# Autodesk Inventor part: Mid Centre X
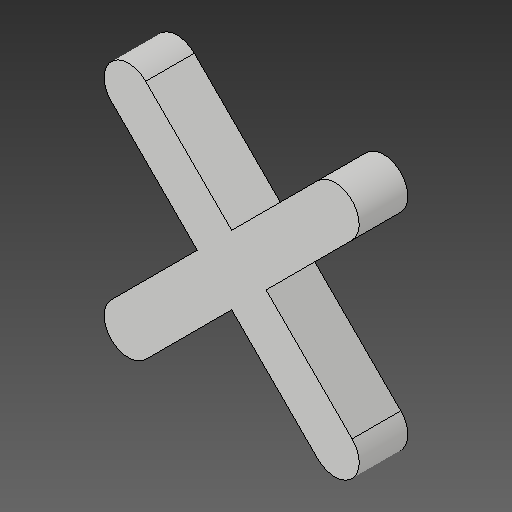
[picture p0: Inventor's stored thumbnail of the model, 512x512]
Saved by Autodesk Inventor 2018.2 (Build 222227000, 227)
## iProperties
Created: 2018-03
Part Number: Mid Centre X
Material: Generic
Document SubType Name: Modeling
Designer: PeterMaxwell-Stewart
Mass: 1.57135 g
Surface Area: 12.8562 cm^2
Volume: 1.57135 cm^3
Density: 1 g/cm^3
Appearance: Default
Author: PeterMaxwell-Stewart
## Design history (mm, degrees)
derived "O's and X's.ipt"
feature "Mid Centre X::O's and X's.ipt" dims "d0" = 10
tag "TaggingFeature1"
body "Solid1"
